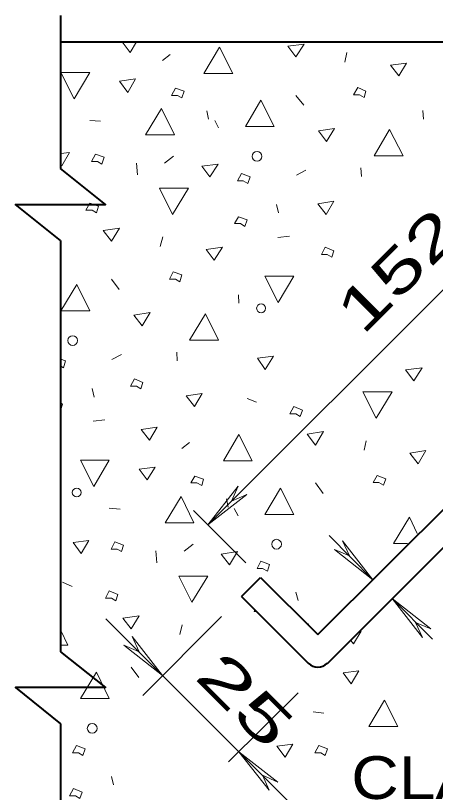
# Model space of a CAD drawing. Extents: x 312583 to 312854, y 144419 to 144597.
# Drawn here: x 312632.98 to 312640.43, y 144462.01 to 144475.81 of the extents above; entities that cross this region are included whole.
import ezdxf

# ---------------------------------------------------------------- set-up
doc = ezdxf.new("R2010")
doc.units = 0
doc.header["$LTSCALE"] = 0.3
doc.layers.add('1', color=7, linetype='Continuous', lineweight=13)

msp = doc.modelspace()

# ---------------------------------------------------------------- linework, layer by layer
at = {"layer": '1', "lineweight": 40}
for p, q in [((312633.776, 144475.8107), (312633.776, 144473.0967)), ((312633.776, 144475.3431), (312646.7174, 144475.3431)), ((312638.3454, 144464.8167), (312645.4907, 144471.9544)), ((312633.776, 144471.8164), (312633.776, 144464.5101)), ((312636.9884, 144465.4914), (312637.3257, 144465.8287)), ((312637.3257, 144465.8287), (312638.3454, 144464.8167)), ((312636.9884, 144465.4914), (312638.1767, 144464.3031)), ((312633.776, 144463.2297), (312633.776, 144459.9867))]:
    msp.add_line(p, q, dxfattribs=at)
at = {"layer": '1'}
for p, q in [((312638.859, 144475.1514), (312638.8207, 144474.9827)), ((312635.7234, 144475.1207), (312635.5854, 144475.0134)), ((312636.3904, 144466.7641), (312644.5247, 144474.8984)), ((312638.0924, 144474.2161), (312637.9544, 144474.3924)), ((312636.375, 144474.1164), (312636.4057, 144473.9707)), ((312640.2084, 144474.1241), (312640.216, 144473.9707)), ((312634.2974, 144473.9477), (312634.489, 144473.9324)), ((312636.513, 144473.9477), (312636.582, 144473.8174)), ((312635.7847, 144473.3114), (312635.6237, 144473.1887)), ((312635.1254, 144473.1887), (312635.1407, 144472.9817)), ((312638.1307, 144473.0661), (312637.962, 144472.9741)), ((312639.1044, 144473.1044), (312639.1197, 144472.9511)), ((312637.6094, 144472.4527), (312637.6477, 144472.3071)), ((312635.593, 144471.8777), (312635.547, 144471.7091)), ((312637.8394, 144471.8931), (312637.6324, 144471.8701)), ((312634.8187, 144470.9424), (312634.6807, 144471.1264)), ((312636.9347, 144470.8504), (312636.9424, 144470.7047)), ((312634.857, 144469.7924), (312634.6884, 144469.7004)), ((312635.8384, 144469.8307), (312635.846, 144469.6774)), ((312634.3357, 144469.1867), (312634.374, 144469.0334)), ((312637.2567, 144468.9414), (312637.088, 144469.0104)), ((312634.5657, 144468.6271), (312634.3587, 144468.6041)), ((312636.0684, 144468.2284), (312635.9304, 144468.1211)), ((312639.204, 144468.2591), (312639.1657, 144468.0904)), ((312636.3904, 144466.7641), (312636.927, 144467.4541)), ((312636.927, 144467.4541), (312636.812, 144467.1857)), ((312638.4374, 144467.3237), (312638.2994, 144467.5077)), ((312636.3904, 144466.7641), (312637.0804, 144467.3007)), ((312637.0804, 144467.3007), (312636.812, 144467.1857)), ((312636.72, 144467.2241), (312636.7507, 144467.0784)), ((312634.6424, 144467.0631), (312634.834, 144467.0401)), ((312637.065, 144466.0894), (312636.1374, 144467.0171)), ((312636.858, 144467.0554), (312636.927, 144466.9251)), ((312639.319, 144465.7904), (312638.5447, 144466.5724)), ((312638.7824, 144466.4804), (312638.905, 144466.2121)), ((312639.319, 144465.7904), (312638.7824, 144466.4804)), ((312639.687, 144466.4344), (312639.9324, 144466.4344)), ((312635.4704, 144466.3041), (312635.4857, 144466.0894)), ((312636.1297, 144466.4191), (312635.9687, 144466.2964)), ((312638.6367, 144466.3271), (312638.905, 144466.2121)), ((312639.319, 144465.7904), (312638.6367, 144466.3271)), ((312633.983, 144465.6677), (312633.8144, 144465.7444)), ((312637.9544, 144465.5681), (312637.9927, 144465.4224)), ((312640.377, 144464.7324), (312639.664, 144465.4531)), ((312639.664, 144465.4531), (312640.2007, 144464.7631)), ((312639.664, 144465.4531), (312640.3464, 144464.9164)), ((312637.9774, 144461.6964), (312634.581, 144465.0927)), ((312635.2404, 144463.7357), (312636.6357, 144465.1387)), ((312635.938, 144464.9854), (312635.892, 144464.8167)), ((312638.1844, 144465.0084), (312638.1537, 144465.0007)), ((312640.2007, 144464.7631), (312640.078, 144465.0314)), ((312640.3464, 144464.9164), (312640.078, 144465.0314)), ((312635.0487, 144464.7784), (312635.1714, 144464.5101)), ((312635.5854, 144464.0884), (312635.0487, 144464.7784)), ((312634.903, 144464.6251), (312635.1714, 144464.5101)), ((312635.5854, 144464.0884), (312634.903, 144464.6251)), ((312635.1637, 144464.0501), (312635.0334, 144464.2341)), ((312636.7584, 144462.5551), (312637.9927, 144463.7817)), ((312638.261, 144463.4444), (312638.4527, 144463.4214)), ((312636.9424, 144462.7314), (312637.6324, 144462.1947)), ((312636.9424, 144462.7314), (312637.479, 144462.0491)), ((312634.6807, 144462.2944), (312634.719, 144462.1487)), ((312637.6324, 144462.1947), (312637.364, 144462.3174)), ((312637.479, 144462.0491), (312637.364, 144462.3174))]:
    msp.add_line(p, q, dxfattribs=at)
for points in [[(312634.8724, 144475.3431), (312635.0104, 144475.1514), (312635.1254, 144475.3431)], [(312640.3157, 144475.3431), (312640.3234, 144475.3354), (312640.3234, 144475.3431)], [(312633.7837, 144473.1657), (312633.799, 144473.1427), (312633.937, 144473.3804), (312633.7837, 144473.3574)], [(312633.7837, 144469.5854), (312633.8297, 144469.5547), (312633.868, 144469.6774), (312633.7837, 144469.7081)], [(312633.776, 144468.7957), (312633.8144, 144468.9107), (312633.7837, 144468.9261)], [(312640.1087, 144466.6107), (312639.9707, 144466.9021), (312639.687, 144466.4344)], [(312637.226, 144465.2537), (312637.2107, 144465.2231), (312637.2567, 144465.2231)], [(312633.7837, 144464.6251), (312633.9064, 144464.6251), (312633.7837, 144464.8857)], [(312638.928, 144464.7094), (312638.974, 144464.6481), (312639.112, 144464.8781), (312639.0967, 144464.8781)]]:
    msp.add_lwpolyline(points, dxfattribs=at)
for points in [[(312637.8087, 144475.2664), (312637.9544, 144475.0747), (312638.1, 144475.3047)], [(312636.3214, 144474.7834), (312636.835, 144474.7834), (312636.5974, 144475.2511)], [(312639.6334, 144474.9291), (312639.779, 144474.7374), (312639.917, 144474.9674)], [(312634.2974, 144474.7987), (312633.7837, 144474.7987), (312634.0214, 144474.3311)], [(312634.8264, 144474.6454), (312634.972, 144474.4461), (312635.11, 144474.6837)], [(312635.8537, 144474.3924), (312635.9304, 144474.3464), (312635.9687, 144474.4691), (312635.8154, 144474.5227), (312635.7464, 144474.3924)], [(312639.0814, 144474.4001), (312639.1657, 144474.3541), (312639.1964, 144474.4691), (312639.0507, 144474.5304), (312638.974, 144474.4001)], [(312637.0574, 144473.8404), (312637.571, 144473.8404), (312637.3334, 144474.3081)], [(312635.2864, 144473.6947), (312635.8, 144473.6947), (312635.57, 144474.1624)], [(312638.353, 144473.7637), (312638.4987, 144473.5721), (312638.6367, 144473.8021)], [(312639.342, 144473.3191), (312639.8557, 144473.3191), (312639.618, 144473.7867)], [(312634.4354, 144473.2194), (312634.512, 144473.1734), (312634.5504, 144473.2961), (312634.397, 144473.3497), (312634.328, 144473.2194)], [(312636.283, 144473.1351), (312636.4287, 144472.9434), (312636.5744, 144473.1734)], [(312637.019, 144472.8744), (312637.1034, 144472.8284), (312637.1417, 144472.9434), (312636.9884, 144473.0047), (312636.9194, 144472.8744)], [(312636.0454, 144472.7441), (312635.5317, 144472.7441), (312635.7617, 144472.2764)], [(312638.3454, 144472.4681), (312638.491, 144472.2764), (312638.629, 144472.5141)], [(312634.3357, 144472.3531), (312634.4124, 144472.3071), (312634.4507, 144472.4221), (312634.2974, 144472.4757), (312634.2284, 144472.3531)], [(312636.973, 144472.1154), (312637.0497, 144472.0617), (312637.088, 144472.1844), (312636.9347, 144472.2381), (312636.8657, 144472.1154)], [(312634.535, 144471.9927), (312634.6807, 144471.8011), (312634.8264, 144472.0311)], [(312636.3597, 144471.6554), (312636.5054, 144471.4637), (312636.651, 144471.6937)], [(312638.5064, 144471.5634), (312638.5907, 144471.5174), (312638.629, 144471.6324), (312638.4757, 144471.6937), (312638.4067, 144471.5634)], [(312635.8154, 144471.1264), (312635.892, 144471.0804), (312635.9304, 144471.2031), (312635.777, 144471.2567), (312635.708, 144471.1264)], [(312637.916, 144471.1801), (312637.4024, 144471.1801), (312637.64, 144470.7124)], [(312633.7837, 144470.5667), (312634.2974, 144470.5667), (312634.0674, 144471.0344)], [(312635.0794, 144470.4901), (312635.225, 144470.2984), (312635.3707, 144470.5361)], [(312636.0684, 144470.0454), (312636.582, 144470.0454), (312636.352, 144470.5131)], [(312637.272, 144469.7234), (312637.41, 144469.5241), (312637.5557, 144469.7617)], [(312639.9017, 144469.5164), (312640.0474, 144469.3247), (312640.193, 144469.5547)], [(312635.1254, 144469.2251), (312635.202, 144469.1791), (312635.2404, 144469.2941), (312635.087, 144469.3554), (312635.018, 144469.2251)], [(312636.007, 144469.0564), (312636.1527, 144468.8647), (312636.2907, 144469.0947)], [(312639.664, 144469.1254), (312639.1427, 144469.1254), (312639.3804, 144468.6577)], [(312637.9544, 144468.7344), (312638.031, 144468.6884), (312638.0694, 144468.8034), (312637.916, 144468.8647), (312637.847, 144468.7344)], [(312635.2097, 144468.4584), (312635.3554, 144468.2667), (312635.4934, 144468.4967)], [(312636.6664, 144467.8987), (312637.18, 144467.8987), (312636.9424, 144468.3664)], [(312638.1537, 144468.3741), (312638.2994, 144468.1824), (312638.445, 144468.4201)], [(312639.9784, 144468.0367), (312640.124, 144467.8451), (312640.262, 144468.0827)], [(312634.6424, 144467.9141), (312634.1287, 144467.9141), (312634.3664, 144467.4464)], [(312635.1714, 144467.7531), (312635.317, 144467.5614), (312635.455, 144467.7914)], [(312636.1987, 144467.5077), (312636.283, 144467.4617), (312636.3137, 144467.5767), (312636.1604, 144467.6304), (312636.0914, 144467.5077)], [(312639.4264, 144467.5154), (312639.5107, 144467.4694), (312639.549, 144467.5844), (312639.3957, 144467.6381), (312639.3267, 144467.5154)], [(312637.4024, 144466.9481), (312637.916, 144466.9481), (312637.6784, 144467.4157)], [(312635.6314, 144466.8024), (312636.145, 144466.8024), (312635.915, 144467.2701)], [(312633.9984, 144466.4497), (312634.144, 144466.2581), (312634.282, 144466.4881)], [(312634.7804, 144466.3347), (312634.857, 144466.2887), (312634.8954, 144466.4037), (312634.742, 144466.4651), (312634.673, 144466.3347)], [(312636.628, 144466.2427), (312636.7737, 144466.0511), (312636.9194, 144466.2887)], [(312637.364, 144465.9897), (312637.4484, 144465.9437), (312637.4867, 144466.0587), (312637.3334, 144466.1201), (312637.2644, 144465.9897)], [(312636.3904, 144465.8517), (312635.8767, 144465.8517), (312636.1067, 144465.3917)], [(312634.6807, 144465.4607), (312634.7574, 144465.4147), (312634.7957, 144465.5297), (312634.6424, 144465.5911), (312634.5734, 144465.4607)], [(312634.88, 144465.1081), (312635.0334, 144464.9164), (312635.1714, 144465.1464)], [(312634.1287, 144463.6821), (312634.6424, 144463.6821), (312634.4124, 144464.1497)], [(312638.79, 144464.1344), (312638.9357, 144463.9427), (312639.0737, 144464.1727)], [(312639.25, 144463.1837), (312639.7637, 144463.1837), (312639.526, 144463.6514)], [(312634.098, 144462.7161), (312634.1747, 144462.6701), (312634.213, 144462.7851), (312634.0597, 144462.8464), (312633.9907, 144462.7161)], [(312637.617, 144462.8311), (312637.7627, 144462.6394), (312637.9007, 144462.8694)], [(312638.399, 144462.7161), (312638.4757, 144462.6701), (312638.514, 144462.7851), (312638.3607, 144462.8464), (312638.2917, 144462.7161)], [(312634.0444, 144461.9494), (312634.121, 144461.9034), (312634.1594, 144462.0184), (312634.006, 144462.0797), (312633.937, 144461.9494)]]:
    msp.add_lwpolyline(points, close=True, dxfattribs=at)
at = {"layer": '1', "lineweight": 40}
for points in [[(312633.776, 144471.8164), (312632.9787, 144472.4527), (312634.5734, 144472.4527), (312633.776, 144473.0967)], [(312638.514, 144464.3031), (312645.9507, 144471.7397), (312646.679, 144472.4681)], [(312633.776, 144464.5101), (312634.5734, 144463.8737), (312632.9787, 144463.8737), (312633.776, 144463.2297)]]:
    msp.add_lwpolyline(points, dxfattribs=at)
at = {"layer": '1'}
for centre, radius in [((312637.265, 144473.3093), 0.0865), ((312637.336, 144470.6104), 0.0784), ((312633.9933, 144470.0377), 0.0865), ((312634.0644, 144467.3388), 0.0784), ((312637.6106, 144466.4204), 0.0865), ((312634.3389, 144463.1487), 0.0865)]:
    msp.add_circle(centre, radius, dxfattribs=at)
at = {"layer": '1', "lineweight": 40}
msp.add_arc((312638.3434, 144464.4751), 0.2396, 225, 315, dxfattribs=at)

# ---------------------------------------------------------------- texts
at = {"layer": '1'}
for s, rotation, width, p in [('152 ', 45, 1.5, (312639.1368, 144470.1147)), ('25', 315, 1.65, (312636.132, 144464.0457))]:
    msp.add_text(s, height=0.76, rotation=rotation, dxfattribs=dict(at, width=width)).set_placement(p)
at = {"layer": '1', "width": 1.15}
msp.add_text('CLASS "C"', height=0.76, dxfattribs=at).set_placement((312638.9357, 144461.8947))

doc.saveas('drawing.dxf')
